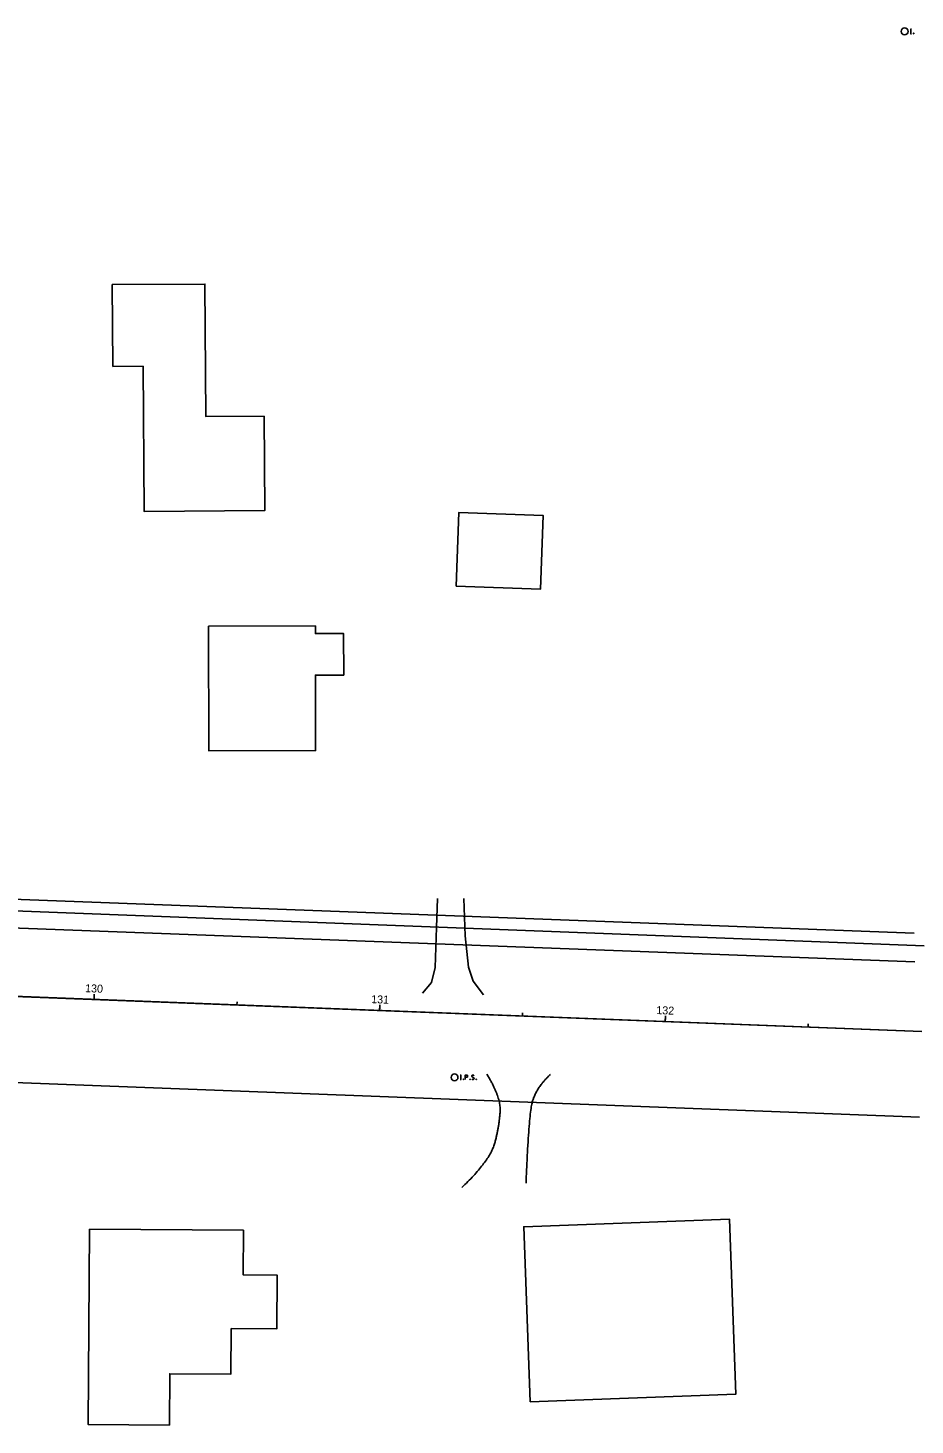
# Model space of a CAD drawing. Extents: x 2003596 to 2006933, y 570827 to 573780.
# Drawn here: x 2005710.9 to 2006021.3, y 572459.6 to 572948.4 of the extents above; entities that cross this region are included whole.
import ezdxf

# ---------------------------------------------------------------- set-up
doc = ezdxf.new("R2010")
doc.units = 0
for name, color, linetype in [('DT_X_Break_Line', 7, 'Continuous'), ('DT_X_Spot_Elev', 7, 'Continuous'), ('DT_X_Void', 7, 'Continuous'), ('GE_X_Alignment', 7, 'Continuous'), ('GE_X_Alignment_1000_Stations', 7, 'Continuous'), ('GE_X_Alignment_100_Stations', 7, 'Continuous'), ('GE_X_Alignment_500_Stations', 7, 'Continuous'), ('RW_X_CL', 7, 'Continuous'), ('RW_X_Esmt_SH', 7, 'Continuous'), ('SC_Scratch10', 7, 'Continuous'), ('SV_P_Mon_Cells_Set', 7, 'Continuous'), ('SV_X_Mon_Cells_Found', 7, 'Continuous'), ('UT_X_Telecom', 7, 'Continuous')]:
    doc.layers.add(name, color=color, linetype=linetype)

msp = doc.modelspace()

# ---------------------------------------------------------------- linework, layer by layer
at = {"layer": 'DT_X_Break_Line'}
for points in [[(2005740.56, 572829.94), (2005740.37, 572858.55), (2005772.82, 572858.77), (2005773.14, 572812.38), (2005793.51, 572812.52), (2005793.73, 572779.5), (2005751.54, 572779.21), (2005751.19, 572830.01)], [(2005860.72, 572753.1), (2005861.71, 572778.88), (2005891.21, 572777.74), (2005890.23, 572751.96)], [(2005774.05, 572739.05), (2005811.45, 572739.13), (2005811.46, 572736.44), (2005821.34, 572736.46), (2005821.37, 572721.97), (2005811.49, 572721.95), (2005811.55, 572695.54), (2005774.15, 572695.45)], [(2005886.65, 572467.73), (2005884.4, 572528.96), (2005956.35, 572531.6), (2005958.6, 572470.38)], [(2005732.44, 572528.13), (2005786.28, 572527.72), (2005786.16, 572512.12), (2005798.09, 572512.03), (2005797.94, 572493.18), (2005782.01, 572493.3), (2005781.89, 572477.37), (2005760.52, 572477.53), (2005760.38, 572459.56), (2005731.92, 572459.77)]]:
    msp.add_lwpolyline(points, close=True, dxfattribs=at)
at = {"layer": 'DT_X_Spot_Elev'}
msp.add_line((2006023.62, 572597.25), (2005654.09, 572611.43), dxfattribs=at)
at = {"layer": 'DT_X_Void'}
for points in [[(2005848.92, 572610.68), (2005852.06, 572614.45), (2005853.42, 572619.69), (2005853.86, 572633.69), (2005854.24, 572643.73)], [(2005863.46, 572643.76), (2005863.92, 572630.72), (2005865.02, 572619.81), (2005866.7, 572614.83), (2005870.25, 572610.04)]]:
    msp.add_lwpolyline(points, dxfattribs=at)
for points in [[(2005871.48, 572582.31), (2005876.3, 572574.44), (2005875.93, 572564.79), (2005872.68, 572552.11), (2005862.67, 572542.64)], [(2005893.73, 572582.24), (2005888.63, 572577.51), (2005886.08, 572567.56), (2005885.18, 572544.14)]]:
    msp.add_open_spline(points, degree=2, dxfattribs=at)
at = {"layer": 'GE_X_Alignment'}
msp.add_line((2005031.48, 572635.32), (2006023.62, 572597.25), dxfattribs=at)
at = {"layer": 'GE_X_Alignment_1000_Stations'}
msp.add_line((2005734.03, 572608.36), (2005734.11, 572610.36), dxfattribs=at)
at = {"layer": 'GE_X_Alignment_100_Stations'}
for p, q in [((2005734.03, 572608.36), (2005734.11, 572610.36)), ((2005784, 572606.44), (2005784.04, 572607.64)), ((2005833.96, 572604.53), (2005834.04, 572606.53)), ((2005883.92, 572602.61), (2005883.97, 572603.81)), ((2005933.89, 572600.69), (2005933.96, 572602.69)), ((2005983.85, 572598.78), (2005983.9, 572599.98))]:
    msp.add_line(p, q, dxfattribs=at)
at = {"layer": 'GE_X_Alignment_500_Stations'}
for p, q in [((2005734.03, 572608.36), (2005734.11, 572610.36)), ((2005833.96, 572604.53), (2005834.01, 572605.73)), ((2005933.89, 572600.69), (2005933.93, 572601.89))]:
    msp.add_line(p, q, dxfattribs=at)
at = {"layer": 'RW_X_CL'}
msp.add_line((2006023.62, 572597.25), (2005031.48, 572635.32), dxfattribs=at)
at = {"layer": 'RW_X_Esmt_SH'}
for p, q in [((2005034.78, 572665.22), (2006024.45, 572627.24)), ((2005028.18, 572605.42), (2006022.8, 572567.26))]:
    msp.add_line(p, q, dxfattribs=at)
at = {"layer": 'SC_Scratch10'}
msp.add_line((2006023.71, 572597.25), (2005465.42, 572618.88), dxfattribs=at)
at = {"layer": 'SV_P_Mon_Cells_Set'}
for points in [[(2005862.17, 572582.02), (2005862.52, 572582.02)], [(2005862.17, 572580.42), (2005862.52, 572580.42)], [(2005862.34, 572580.42), (2005862.34, 572582.02)], [(2005863.3, 572580.63), (2005863.36, 572580.63), (2005863.39, 572580.6), (2005863.42, 572580.55), (2005863.42, 572580.49), (2005863.39, 572580.44), (2005863.36, 572580.42), (2005863.3, 572580.42), (2005863.27, 572580.44), (2005863.24, 572580.49), (2005863.24, 572580.55), (2005863.27, 572580.6), (2005863.3, 572580.63)], [(2005863.91, 572580.42), (2005863.91, 572582.02), (2005864.44, 572582.02), (2005864.49, 572582), (2005864.57, 572581.98), (2005864.6, 572581.95), (2005864.64, 572581.93), (2005864.68, 572581.86), (2005864.71, 572581.8), (2005864.74, 572581.7), (2005864.74, 572581.55), (2005864.72, 572581.5), (2005864.7, 572581.42), (2005864.66, 572581.33), (2005864.61, 572581.3), (2005864.58, 572581.27), (2005864.53, 572581.25), (2005864.44, 572581.23), (2005863.91, 572581.23)], [(2005865.55, 572580.63), (2005865.61, 572580.63), (2005865.64, 572580.6), (2005865.67, 572580.55), (2005865.67, 572580.49), (2005865.64, 572580.44), (2005865.61, 572580.42), (2005865.55, 572580.42), (2005865.52, 572580.44), (2005865.48, 572580.49), (2005865.48, 572580.55), (2005865.52, 572580.6), (2005865.55, 572580.63)], [(2005866.92, 572581.9), (2005866.9, 572581.93), (2005866.86, 572581.95), (2005866.76, 572581.99), (2005866.64, 572582.02), (2005866.55, 572582.02), (2005866.52, 572582.02), (2005866.38, 572581.98), (2005866.26, 572581.9), (2005866.18, 572581.8), (2005866.16, 572581.7), (2005866.16, 572581.62), (2005866.18, 572581.52), (2005866.27, 572581.44), (2005866.87, 572581.06), (2005866.93, 572581.01), (2005866.95, 572580.96), (2005866.97, 572580.88), (2005866.97, 572580.81), (2005866.96, 572580.73), (2005866.95, 572580.68), (2005866.93, 572580.62), (2005866.91, 572580.57), (2005866.88, 572580.53), (2005866.85, 572580.49), (2005866.82, 572580.47), (2005866.77, 572580.44), (2005866.74, 572580.43), (2005866.64, 572580.42), (2005866.49, 572580.42), (2005866.39, 572580.44), (2005866.25, 572580.53), (2005866.16, 572580.6)], [(2005867.73, 572580.63), (2005867.79, 572580.63), (2005867.82, 572580.6), (2005867.85, 572580.55), (2005867.85, 572580.49), (2005867.82, 572580.44), (2005867.79, 572580.42), (2005867.73, 572580.42), (2005867.7, 572580.44), (2005867.67, 572580.49), (2005867.67, 572580.55), (2005867.7, 572580.6), (2005867.73, 572580.63)]]:
    msp.add_lwpolyline(points, dxfattribs=at)
msp.add_circle((2005860.15, 572581.21), 1.2, dxfattribs=at)
at = {"layer": 'SV_X_Mon_Cells_Found'}
for points in [[(2006019.68, 572947.96), (2006020.03, 572947.96)], [(2006019.85, 572946.36), (2006019.85, 572947.96)], [(2006019.68, 572946.36), (2006020.03, 572946.36)], [(2006020.81, 572946.58), (2006020.87, 572946.58), (2006020.9, 572946.55), (2006020.93, 572946.5), (2006020.93, 572946.44), (2006020.9, 572946.39), (2006020.87, 572946.36), (2006020.81, 572946.36), (2006020.78, 572946.39), (2006020.75, 572946.44), (2006020.75, 572946.5), (2006020.78, 572946.55), (2006020.81, 572946.58)]]:
    msp.add_lwpolyline(points, dxfattribs=at)
msp.add_circle((2006017.66, 572947.16), 1.2, dxfattribs=at)
at = {"layer": 'UT_X_Telecom'}
for points in [[(2005147.76, 572660.26), (2005421.1, 572658.32), (2005446.17, 572659.8), (2005471.38, 572659.28), (2005497.09, 572658.54), (2005522.25, 572656.73), (2005547.24, 572652.92), (2005571.87, 572650.16), (2005596.85, 572649.37), (2005621.79, 572646.67), (2006021.03, 572631.61)], [(2005147.98, 572650.26), (2005421.36, 572648.31), (2005446.36, 572649.8), (2005471.14, 572649.29), (2005496.59, 572648.55), (2005521.14, 572646.78), (2005545.93, 572643), (2005571.15, 572640.18), (2005596.15, 572639.39), (2005621.06, 572636.69), (2006021.19, 572621.6)]]:
    msp.add_lwpolyline(points, dxfattribs=at)

# ---------------------------------------------------------------- texts
at = {"layer": 'GE_X_Alignment_1000_Stations'}
msp.add_text('130', height=2.8, rotation=357.8026, dxfattribs=at).set_placement((2005730.85, 572611.03))
at = {"layer": 'GE_X_Alignment_100_Stations'}
for s, p in [('130', (2005730.85, 572611.03)), ('131', (2005830.95, 572607.19)), ('132', (2005930.71, 572603.36))]:
    msp.add_text(s, height=2.8, rotation=357.8026, dxfattribs=at).set_placement(p)
at = {"layer": 'GE_X_Alignment_500_Stations'}
msp.add_text('130', height=2.8, rotation=357.8026, dxfattribs=at).set_placement((2005730.85, 572611.03))

doc.saveas('drawing.dxf')
